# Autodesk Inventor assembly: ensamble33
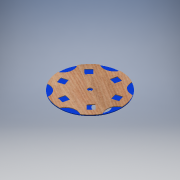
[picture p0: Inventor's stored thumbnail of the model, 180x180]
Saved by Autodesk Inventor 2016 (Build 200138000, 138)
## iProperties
Created: 2016-06
Part Number: ensamble33
Material: Genérico
Document SubType Name: Assembly
Designer: adm
Author: adm
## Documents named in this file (3)
- C:\Users\adm\Desktop\ensamble33.iam
- C:\Users\adm\Desktop\circulo1.ipt
- C:\Users\adm\Desktop\circulo2.ipt
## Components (2 placed, 2 different names)
1. circulo1:1 — Coincidencia:1, Coincidencia:2
2. circulo2:1 — Coincidencia:1, Coincidencia:2
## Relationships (2: Mate 2)
- Coincidencia:1 [Mate]: circulo1:1 ↔ circulo2:1
- Coincidencia:2 [Mate]: circulo1:1 ↔ circulo2:1
